(* Logix 5000 project; controller EFlo_iQ_Controller vendor 1 type 14 code 74 rev 20.12; software revision 20.01 *)

TASK MainTask (continuous, watchdog 500 ms) : MainProgram

MODULES
   Local : vendor 1 type 14 code 74 (1768Ctrl5Slot 0, Compact 0, rev 20.12)
      ENET : 1768-ENBT (1768 1, Ethernet 10.10.20.11, rev 3.1)
         EFlo_iQ : ETHERNET-MODULE (Ethernet 192.168.2.16, rev 1.1, Output RPI 10 ms)   // Graco E-Flo iQ Advanced Heat Map
END_MODULES

TYPE ActivePump :
STRUCT
   ControlBits : EFlo_iQ_Control_Bits;
   StatusBits : EFlo_iQ_Status_Bits;
   Information : EFlo_iQ_Pump_Information;
   AdditionalInformation : EFlo_iQ_Pump_Information_ActivePumpOnly;
   DispenseInformation : EFlo_iQ_Dispense_Information;
   StyleInformation : E_Flo_iQ_Style;
   HeartbeatLogic : EFlo_iQ_HeartbeatLogic;
   DataExchange : EFlo_iQ_Pump_Data_Exchange;
END_STRUCT
END_TYPE

TYPE E_Flo_iQ_Style :
STRUCT
   DesiredActiveStyleNumber : INT;
   StyleFieldbusPrechargeRequested : INT;   // XXXX.X bars
   StyleFieldbusFlowrateRequested : INT;   // XXXX cc/min
   StyleFieldbusShotSizeRequested : INT;   // XXXX.XX cc
   StyleFieldbusDValveOnDelayRequested : INT;   // XXXX ms
   StyleFieldbusDValveOffDelayRequested : INT;   // XXXX ms
   StyleFieldbusMotorOnDelayRequested : INT;   // XXXX ms
   StyleFieldbusMotorOffDelayRequested : INT;   // XXXX ms
   ActiveStyleLoaded : INT;
   ActiveStylePrecharge : INT;   // XXXX.X bars
   ActiveStyleFlowrate : INT;   // XXXX cc/min
   ActiveStyleShotSize : INT;   // XXXX.XX cc
   ActiveStyleDispenseValveOnDelay : INT;   // XXXX ms
   ActiveStyleDispenseValveOffDelay : INT;   // XXXX ms
   ActiveStyleMotorOnDelay : INT;   // XXXX ms
   ActiveStyleMotorOffDelay : INT;   // XXXX ms
   ActualStyleFieldbusRequestPrecharge : INT;   // XXXX.X bars
   ActualStyleFieldbusRequestFlowrate : INT;   // XXXX cc/min
   ActualStyleFieldbusRequestShotSize : INT;   // XXXX.XX cc
   ActualStyleFieldbusRequestDValveOnDeley : INT;   // XXXX ms
   ActualStyleFieldbusRequestDValveOffDeley : INT;   // XXXX ms
   ActualStyleFieldbusRequestMotorOnDelay : INT;   // XXXX ms
   ActualStyleFieldbusRequestMotorOffDelay : INT;   // XXXX ms
END_STRUCT
END_TYPE

TYPE EFlo_iQ_Control_Bits :
STRUCT
   SystemEnableRequest : BOOL;
   SystemDisableRequest : BOOL;
   PLCLockoutRequest : BOOL;
   StyleEnableSignal : BOOL;
   StyleGoSignal : BOOL;
   StyleDispenseCompleted : BOOL;
   TandemCrossoverRequest : BOOL;
   PrimingRequest : BOOL;
   ValveDepressurizationRequest : BOOL;
   PlatenDepressurizationRequest : BOOL;
   AutoDepressurizationCancelRequest : BOOL;
   AcknowledgeClearErrorsRequest : BOOL;
END_STRUCT
END_TYPE

TYPE EFlo_iQ_Dispense_Information :
STRUCT
   ActualAmountDispense : DINT;   // XXXX.XX cc
   ActualShotSizeRequested : DINT;   // XXXX.XX cc
END_STRUCT
END_TYPE

TYPE EFlo_iQ_HeartbeatLogic :
STRUCT
   HeartbeatFailure : BOOL;
   EFlo_iQ_Disconnected : BOOL;
   Heartbeat_HighMonitor : COUNTER;
   Heartbeat_LowMonitor : COUNTER;
   Heartbeat_MonitorTimer : TIMER;
   Heartbeat_StopMonitorTimer : BOOL;
END_STRUCT
END_TYPE

TYPE EFlo_iQ_Pump_Data_Exchange :
STRUCT
   PumpDataExchangeActiveCommand : INT;
   PumpDataExchangeActiveValue : DINT;
END_STRUCT
END_TYPE

TYPE EFlo_iQ_Pump_Information :
STRUCT
   ActualPumpFlowrate : INT;   // XXXX cc/min
   OutletPumpPressure : INT;   // XXXX.X bars
END_STRUCT
END_TYPE

TYPE EFlo_iQ_Pump_Information_ActivePumpOnly :
STRUCT
   ValvePressure : INT;   // XXXX.X bars
   PumpPosition : INT;   // X.XXXX inches
   PrimeFlowrateTarget : INT;   // XXXX cc/min
   PrimePressureTarget : INT;   // XXXX.X bars
END_STRUCT
END_TYPE

TYPE EFlo_iQ_Status_Bits :
STRUCT
   Heartbeat : BOOL;
   AutomationReady : BOOL;
   PLCControlActive : BOOL;
   SystemActive : BOOL;
   NoAlarmsPresent : BOOL;
   NoDeviationsPresent : BOOL;
   NoAdvisoriesPresent : BOOL;
   SystemReadyToDispense : BOOL;
   PrechargeDechargeActive : BOOL;
   DispenseInProcess : BOOL;
   DrumIsLow : BOOL;
   DrumIsEmpty : BOOL;
   PumpNotPrimed : BOOL;
   PumpInJobCycle : BOOL;
   PrimingActive : BOOL;
   ValveDepressurizationActive : BOOL;
   PlatenDepressurizationActive : BOOL;
   AutoDepressurizationActive : BOOL;
   AutoDepressurizationHappened : BOOL;
   PumpIsTryingToMove : BOOL;
   PumpIsActuallyMoving : BOOL;
   DispenseValveOpened : BOOL;
   PlatenValveOpened : BOOL;
   TandemActivePump : BOOL;   // 0 = Pump 1 1 = Pump 2
   iQModeActive : BOOL;
   ChangeoverHappenedDuringDispense : BOOL;
END_STRUCT
END_TYPE

TYPE EFlo_iQ_System_Data_Exchange :
STRUCT
   DesiredDataExchangeCommand : INT;
END_STRUCT
END_TYPE

TYPE Heat_Control_Bits :
STRUCT
   SystemEnabledRequest : BOOL;
   SystemDisabledRequest : BOOL;
   PLCLockoutRequest : BOOL;
   HeatOnRequest : BOOL;
   HeatOffRequest : BOOL;
   HeatSetbackRequest : BOOL;
   AcknowledgeClearErrors : BOOL;
END_STRUCT
END_TYPE

TYPE Heat_Data_Exchange :
STRUCT
   HeatDataExchangeActiveCommand : INT;
   HeatDataExchangeActiveValue : DINT;
   HeatDataExchangeDesiredCommand : INT;
   HeatDataExchangeDesiredValue : DINT;
END_STRUCT
END_TYPE

TYPE Heat_HeartbeatLogic :
STRUCT
   HeartbeatFailure : BOOL;
   Heat_Disconnected : BOOL;
   Heartbeat_HighMonitor : COUNTER;
   Heartbeat_LowMonitor : COUNTER;
   Heartbeat_MonitorTimer : TIMER;
   Heartbeat_StopMonitorTimer : BOOL;
END_STRUCT
END_TYPE

TYPE Heat_Information :
STRUCT
   ModuleHeatSoakTimeRemaining : INT;   // XXX seconds
END_STRUCT
END_TYPE

TYPE Heat_Module :
STRUCT
   Control_Bits : Heat_Control_Bits;
   Status_Bits : Heat_Status_Bits;
   DataExchange : Heat_Data_Exchange;
   Information : Heat_Information;
   Heartbeat_Logic : Heat_HeartbeatLogic;
END_STRUCT
END_TYPE

TYPE Heat_Status_Bits :
STRUCT
   HeartbeatToPLC : BOOL;
   SystemHeatEnabled : BOOL;
   PLCControlLockActive : BOOL;
   HeatIsOn : BOOL;
   HeatIsWarmingUp : BOOL;
   HeatIsAtTemperature : BOOL;
   HeatIsInTempeatureSoak : BOOL;
   HeatIsInSetback : BOOL;
   HeatIsOff : BOOL;
   NoHeatModuleAlarmsPresent : BOOL;
   NoHeatModuleDeviationsPresent : BOOL;
   NoHeatModuleAdvisoriesPresent : BOOL;
   NoHeatZonesAlarmsPresent : BOOL;
   NoHeatZonesDeviationsPresent : BOOL;
   NoHeatZonesAdvisoriesPresent : BOOL;
   HeatIdleTimeoutHappened : BOOL;
END_STRUCT
END_TYPE

TYPE InactivePump :
STRUCT
   StatusBits : EFlo_iQ_Status_Bits;
   Information : EFlo_iQ_Pump_Information;
   DataExchangeOutputs : EFlo_iQ_Pump_Data_Exchange;
   HeartbeatLogic : EFlo_iQ_HeartbeatLogic;
END_STRUCT
END_TYPE

VAR_GLOBAL   (* controller tags *)
   ActivePump : ActivePump;
   Heat_Module_One : Heat_Module := (Heartbeat_Logic.Heartbeat_HighMonitor.PRE := 2, Heartbeat_Logic.Heartbeat_LowMonitor.PRE := 2, Heartbeat_Logic.Heartbeat_MonitorTimer.PRE := 20000);
   Heat_Module_Two : Heat_Module := (Heartbeat_Logic.Heartbeat_HighMonitor.PRE := 2, Heartbeat_Logic.Heartbeat_LowMonitor.PRE := 2, Heartbeat_Logic.Heartbeat_MonitorTimer.PRE := 20000);
   InactivePump : InactivePump;
   PumpsDesiredDataExchange : EFlo_iQ_System_Data_Exchange;
END_VAR

PROGRAM MainProgram   (* main routine MainRoutine *)

ROUTINE EFlo_iQ_Data_Mapping   (* ladder *)
// Mapping_EFlo_iQ_Data_To_Tags
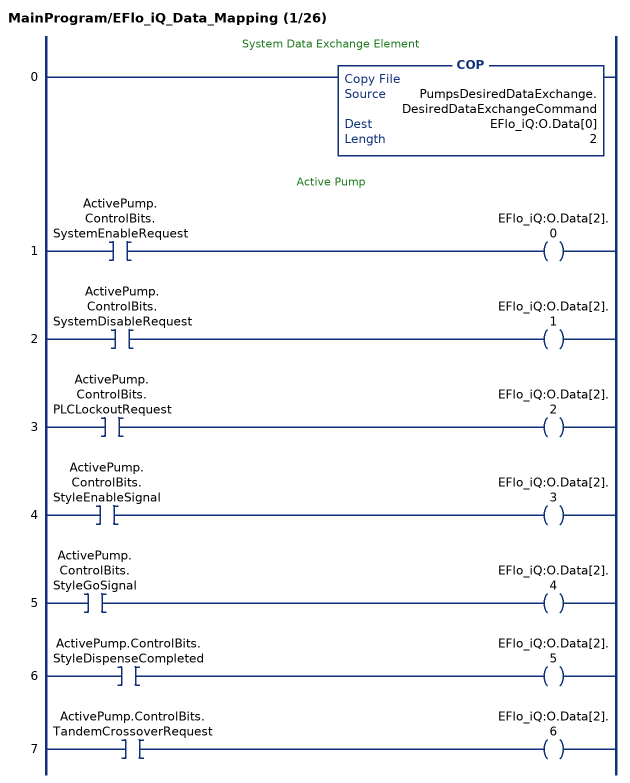
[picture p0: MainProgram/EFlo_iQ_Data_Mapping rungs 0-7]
   // System Data Exchange Element
   0: COP(PumpsDesiredDataExchange.DesiredDataExchangeCommand,EFlo_iQ:O.Data[0],2);
   // Active Pump
   1: XIC(ActivePump.ControlBits.SystemEnableRequest)OTE(EFlo_iQ:O.Data[2].0);
   2: XIC(ActivePump.ControlBits.SystemDisableRequest)OTE(EFlo_iQ:O.Data[2].1);
   3: XIC(ActivePump.ControlBits.PLCLockoutRequest)OTE(EFlo_iQ:O.Data[2].2);
   4: XIC(ActivePump.ControlBits.StyleEnableSignal)OTE(EFlo_iQ:O.Data[2].3);
   5: XIC(ActivePump.ControlBits.StyleGoSignal)OTE(EFlo_iQ:O.Data[2].4);
   6: XIC(ActivePump.ControlBits.StyleDispenseCompleted)OTE(EFlo_iQ:O.Data[2].5);
   7: XIC(ActivePump.ControlBits.TandemCrossoverRequest)OTE(EFlo_iQ:O.Data[2].6);
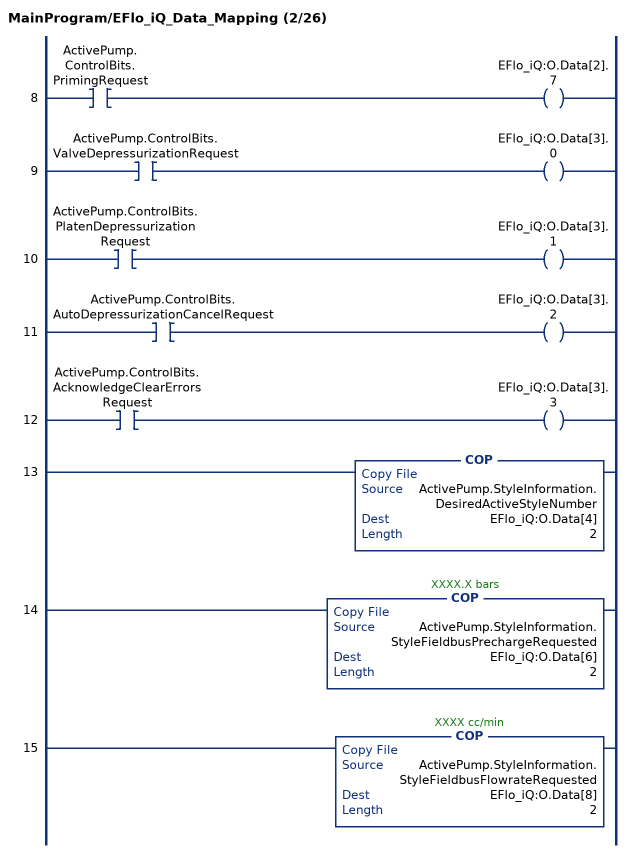
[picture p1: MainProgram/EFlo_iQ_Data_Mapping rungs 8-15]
   8: XIC(ActivePump.ControlBits.PrimingRequest)OTE(EFlo_iQ:O.Data[2].7);
   9: XIC(ActivePump.ControlBits.ValveDepressurizationRequest)OTE(EFlo_iQ:O.Data[3].0);
   10: XIC(ActivePump.ControlBits.PlatenDepressurizationRequest)OTE(EFlo_iQ:O.Data[3].1);
   11: XIC(ActivePump.ControlBits.AutoDepressurizationCancelRequest)OTE(EFlo_iQ:O.Data[3].2);
   12: XIC(ActivePump.ControlBits.AcknowledgeClearErrorsRequest)OTE(EFlo_iQ:O.Data[3].3);
   13: COP(ActivePump.StyleInformation.DesiredActiveStyleNumber,EFlo_iQ:O.Data[4],2);
   14: COP(ActivePump.StyleInformation.StyleFieldbusPrechargeRequested,EFlo_iQ:O.Data[6],2);
   15: COP(ActivePump.StyleInformation.StyleFieldbusFlowrateRequested,EFlo_iQ:O.Data[8],2);
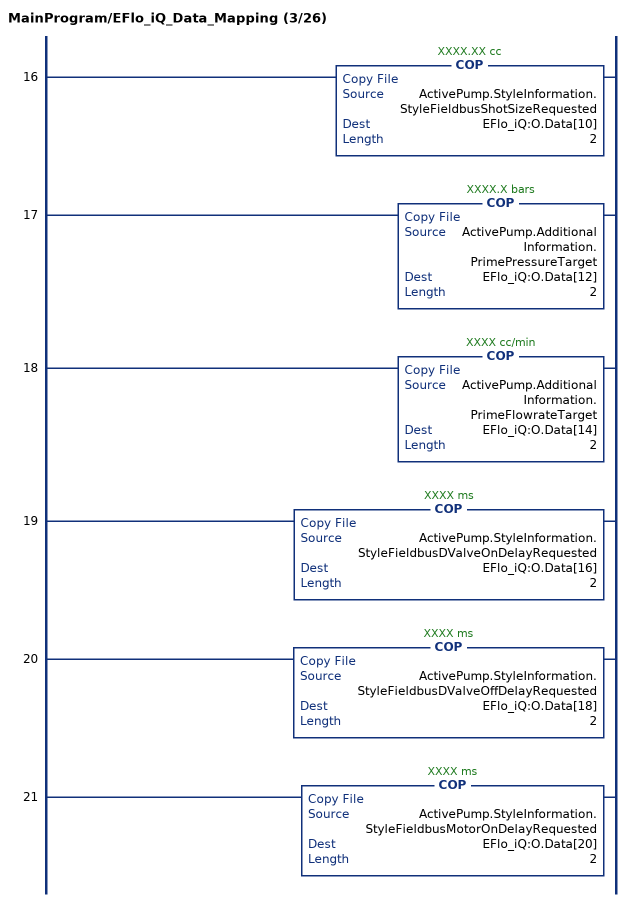
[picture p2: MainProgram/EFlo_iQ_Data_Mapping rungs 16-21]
   16: COP(ActivePump.StyleInformation.StyleFieldbusShotSizeRequested,EFlo_iQ:O.Data[10],2);
   17: COP(ActivePump.AdditionalInformation.PrimePressureTarget,EFlo_iQ:O.Data[12],2);
   18: COP(ActivePump.AdditionalInformation.PrimeFlowrateTarget,EFlo_iQ:O.Data[14],2);
   19: COP(ActivePump.StyleInformation.StyleFieldbusDValveOnDelayRequested,EFlo_iQ:O.Data[16],2);
   20: COP(ActivePump.StyleInformation.StyleFieldbusDValveOffDelayRequested,EFlo_iQ:O.Data[18],2);
   21: COP(ActivePump.StyleInformation.StyleFieldbusMotorOnDelayRequested,EFlo_iQ:O.Data[20],2);
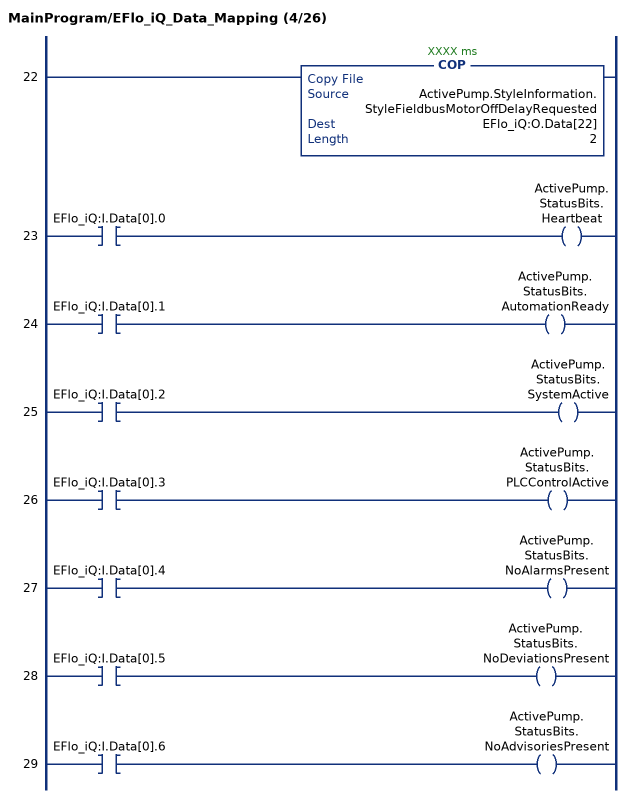
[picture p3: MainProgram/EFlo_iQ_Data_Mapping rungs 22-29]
   22: COP(ActivePump.StyleInformation.StyleFieldbusMotorOffDelayRequested,EFlo_iQ:O.Data[22],2);
   23: XIC(EFlo_iQ:I.Data[0].0)OTE(ActivePump.StatusBits.Heartbeat);
   24: XIC(EFlo_iQ:I.Data[0].1)OTE(ActivePump.StatusBits.AutomationReady);
   25: XIC(EFlo_iQ:I.Data[0].2)OTE(ActivePump.StatusBits.SystemActive);
   26: XIC(EFlo_iQ:I.Data[0].3)OTE(ActivePump.StatusBits.PLCControlActive);
   27: XIC(EFlo_iQ:I.Data[0].4)OTE(ActivePump.StatusBits.NoAlarmsPresent);
   28: XIC(EFlo_iQ:I.Data[0].5)OTE(ActivePump.StatusBits.NoDeviationsPresent);
   29: XIC(EFlo_iQ:I.Data[0].6)OTE(ActivePump.StatusBits.NoAdvisoriesPresent);
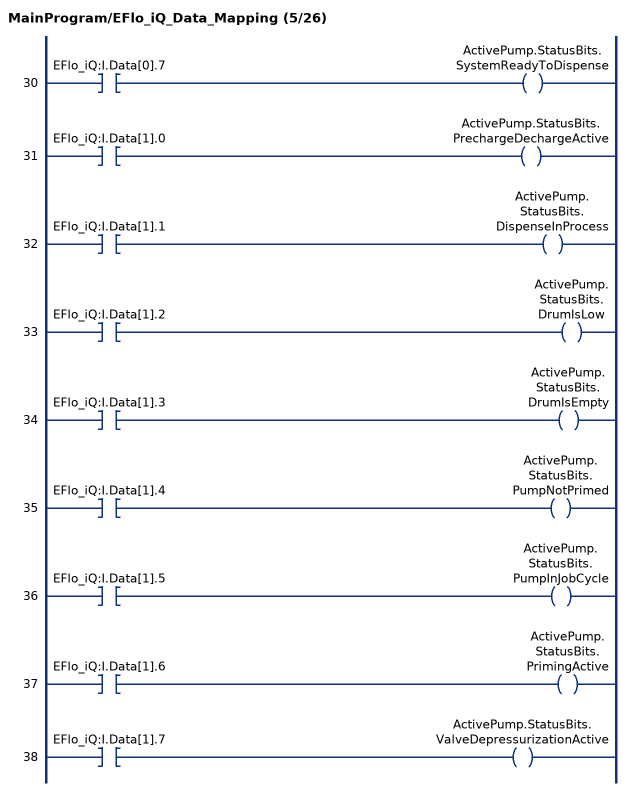
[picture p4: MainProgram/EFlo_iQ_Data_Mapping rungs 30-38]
   30: XIC(EFlo_iQ:I.Data[0].7)OTE(ActivePump.StatusBits.SystemReadyToDispense);
   31: XIC(EFlo_iQ:I.Data[1].0)OTE(ActivePump.StatusBits.PrechargeDechargeActive);
   32: XIC(EFlo_iQ:I.Data[1].1)OTE(ActivePump.StatusBits.DispenseInProcess);
   33: XIC(EFlo_iQ:I.Data[1].2)OTE(ActivePump.StatusBits.DrumIsLow);
   34: XIC(EFlo_iQ:I.Data[1].3)OTE(ActivePump.StatusBits.DrumIsEmpty);
   35: XIC(EFlo_iQ:I.Data[1].4)OTE(ActivePump.StatusBits.PumpNotPrimed);
   36: XIC(EFlo_iQ:I.Data[1].5)OTE(ActivePump.StatusBits.PumpInJobCycle);
   37: XIC(EFlo_iQ:I.Data[1].6)OTE(ActivePump.StatusBits.PrimingActive);
   38: XIC(EFlo_iQ:I.Data[1].7)OTE(ActivePump.StatusBits.ValveDepressurizationActive);
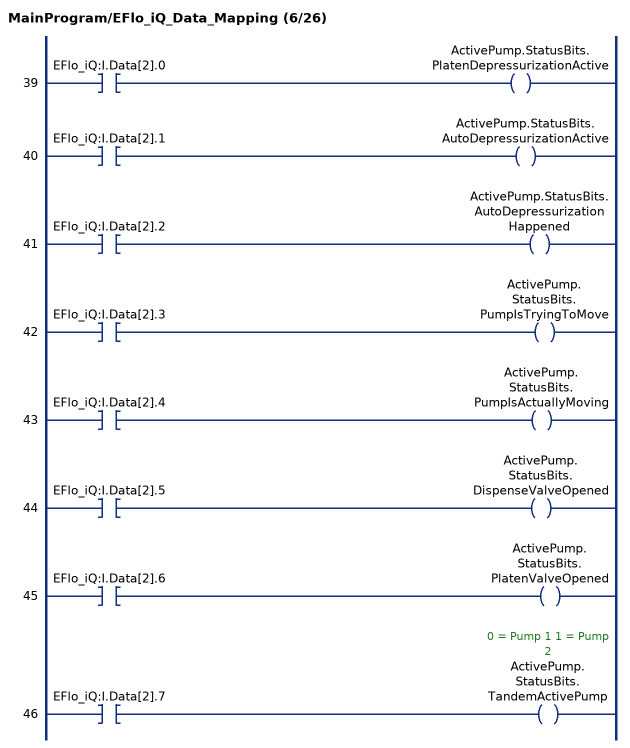
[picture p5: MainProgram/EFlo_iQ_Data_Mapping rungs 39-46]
   39: XIC(EFlo_iQ:I.Data[2].0)OTE(ActivePump.StatusBits.PlatenDepressurizationActive);
   40: XIC(EFlo_iQ:I.Data[2].1)OTE(ActivePump.StatusBits.AutoDepressurizationActive);
   41: XIC(EFlo_iQ:I.Data[2].2)OTE(ActivePump.StatusBits.AutoDepressurizationHappened);
   42: XIC(EFlo_iQ:I.Data[2].3)OTE(ActivePump.StatusBits.PumpIsTryingToMove);
   43: XIC(EFlo_iQ:I.Data[2].4)OTE(ActivePump.StatusBits.PumpIsActuallyMoving);
   44: XIC(EFlo_iQ:I.Data[2].5)OTE(ActivePump.StatusBits.DispenseValveOpened);
   45: XIC(EFlo_iQ:I.Data[2].6)OTE(ActivePump.StatusBits.PlatenValveOpened);
   46: XIC(EFlo_iQ:I.Data[2].7)OTE(ActivePump.StatusBits.TandemActivePump);
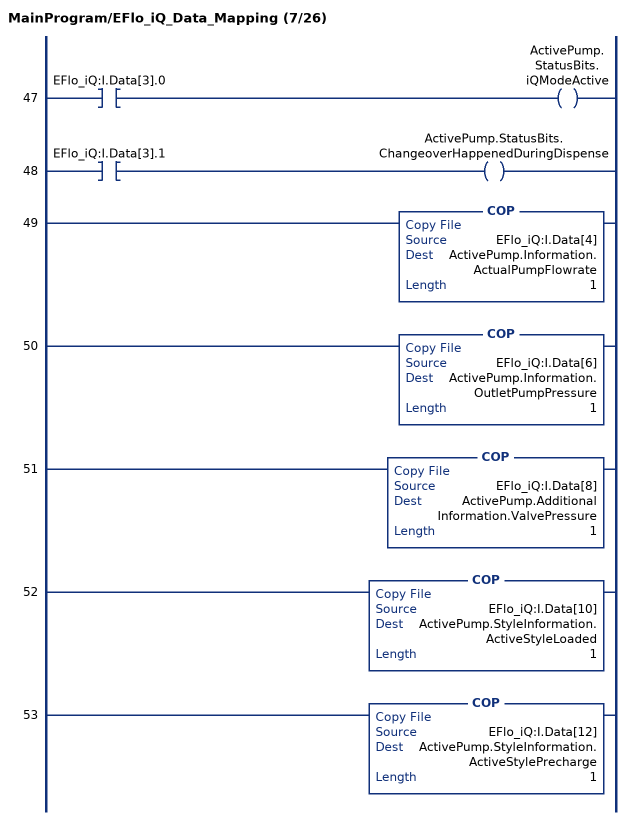
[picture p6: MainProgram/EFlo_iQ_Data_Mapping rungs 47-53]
   47: XIC(EFlo_iQ:I.Data[3].0)OTE(ActivePump.StatusBits.iQModeActive);
   48: XIC(EFlo_iQ:I.Data[3].1)OTE(ActivePump.StatusBits.ChangeoverHappenedDuringDispense);
   49: COP(EFlo_iQ:I.Data[4],ActivePump.Information.ActualPumpFlowrate,1);
   50: COP(EFlo_iQ:I.Data[6],ActivePump.Information.OutletPumpPressure,1);
   51: COP(EFlo_iQ:I.Data[8],ActivePump.AdditionalInformation.ValvePressure,1);
   52: COP(EFlo_iQ:I.Data[10],ActivePump.StyleInformation.ActiveStyleLoaded,1);
   53: COP(EFlo_iQ:I.Data[12],ActivePump.StyleInformation.ActiveStylePrecharge,1);
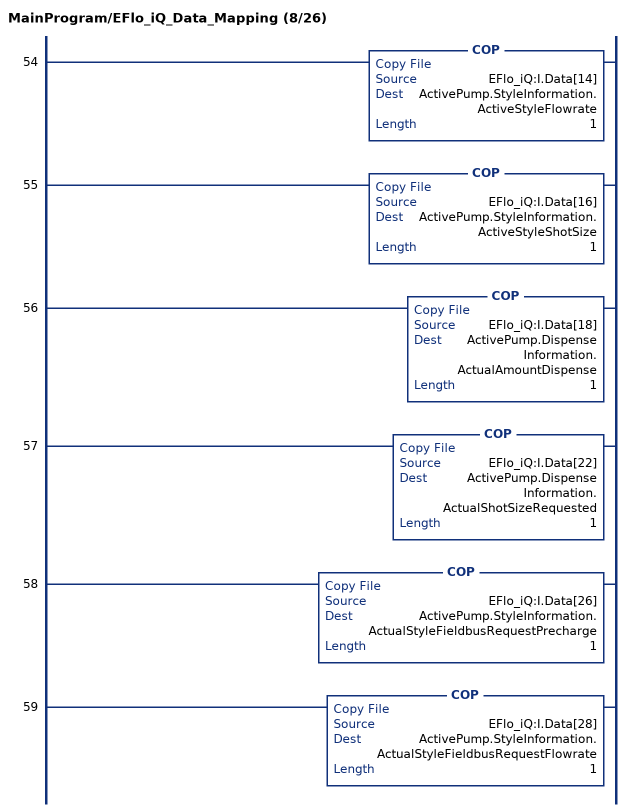
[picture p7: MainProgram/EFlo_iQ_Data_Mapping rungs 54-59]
   54: COP(EFlo_iQ:I.Data[14],ActivePump.StyleInformation.ActiveStyleFlowrate,1);
   55: COP(EFlo_iQ:I.Data[16],ActivePump.StyleInformation.ActiveStyleShotSize,1);
   56: COP(EFlo_iQ:I.Data[18],ActivePump.DispenseInformation.ActualAmountDispense,1);
   57: COP(EFlo_iQ:I.Data[22],ActivePump.DispenseInformation.ActualShotSizeRequested,1);
   58: COP(EFlo_iQ:I.Data[26],ActivePump.StyleInformation.ActualStyleFieldbusRequestPrecharge,1);
   59: COP(EFlo_iQ:I.Data[28],ActivePump.StyleInformation.ActualStyleFieldbusRequestFlowrate,1);
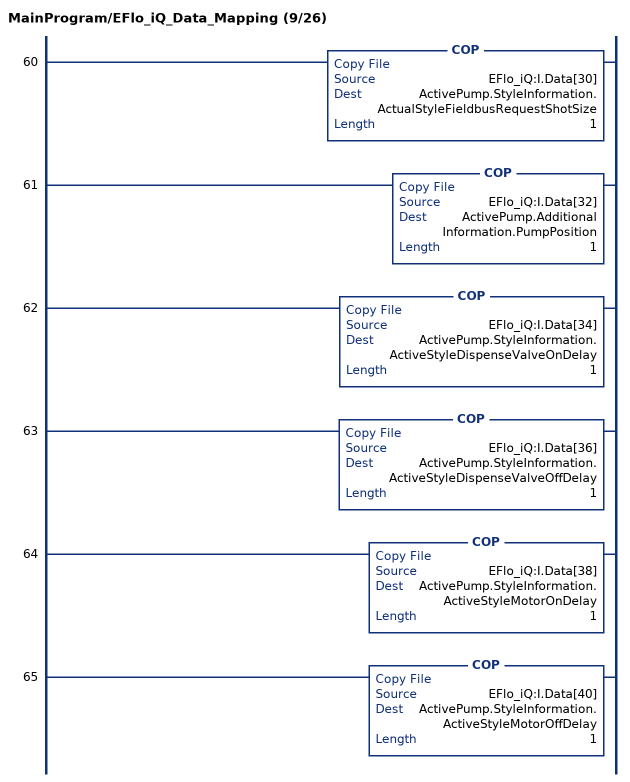
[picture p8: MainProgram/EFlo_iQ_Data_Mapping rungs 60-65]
   60: COP(EFlo_iQ:I.Data[30],ActivePump.StyleInformation.ActualStyleFieldbusRequestShotSize,1);
   61: COP(EFlo_iQ:I.Data[32],ActivePump.AdditionalInformation.PumpPosition,1);
   62: COP(EFlo_iQ:I.Data[34],ActivePump.StyleInformation.ActiveStyleDispenseValveOnDelay,1);
   63: COP(EFlo_iQ:I.Data[36],ActivePump.StyleInformation.ActiveStyleDispenseValveOffDelay,1);
   64: COP(EFlo_iQ:I.Data[38],ActivePump.StyleInformation.ActiveStyleMotorOnDelay,1);
   65: COP(EFlo_iQ:I.Data[40],ActivePump.StyleInformation.ActiveStyleMotorOffDelay,1);
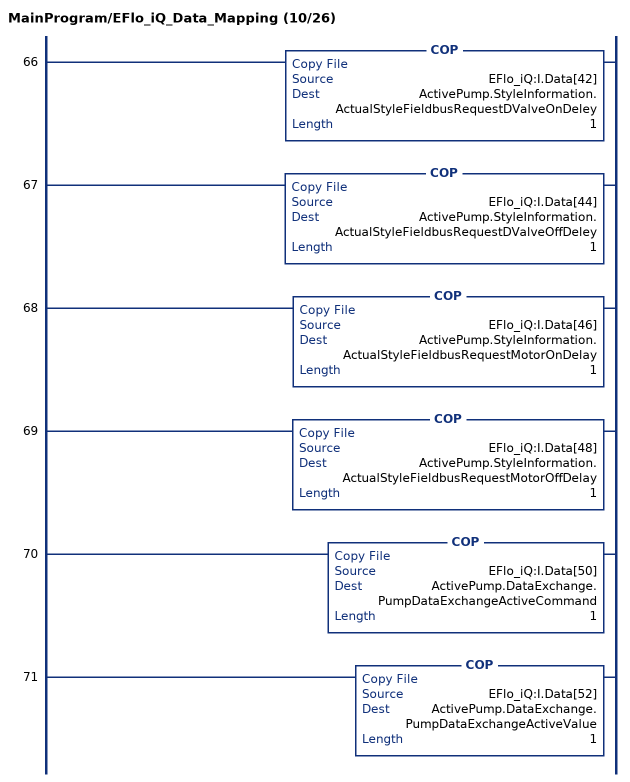
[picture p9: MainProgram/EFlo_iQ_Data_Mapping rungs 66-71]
   66: COP(EFlo_iQ:I.Data[42],ActivePump.StyleInformation.ActualStyleFieldbusRequestDValveOnDeley,1);
   67: COP(EFlo_iQ:I.Data[44],ActivePump.StyleInformation.ActualStyleFieldbusRequestDValveOffDeley,1);
   68: COP(EFlo_iQ:I.Data[46],ActivePump.StyleInformation.ActualStyleFieldbusRequestMotorOnDelay,1);
   69: COP(EFlo_iQ:I.Data[48],ActivePump.StyleInformation.ActualStyleFieldbusRequestMotorOffDelay,1);
   70: COP(EFlo_iQ:I.Data[50],ActivePump.DataExchange.PumpDataExchangeActiveCommand,1);
   71: COP(EFlo_iQ:I.Data[52],ActivePump.DataExchange.PumpDataExchangeActiveValue,1);
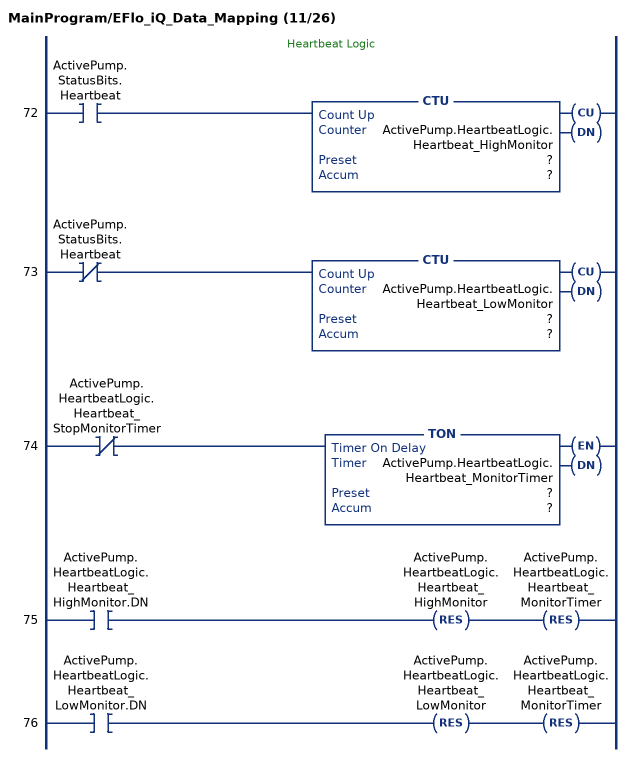
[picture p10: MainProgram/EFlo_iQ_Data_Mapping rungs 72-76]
   // Heartbeat Logic
   72: XIC(ActivePump.StatusBits.Heartbeat)CTU(ActivePump.HeartbeatLogic.Heartbeat_HighMonitor,?,?);
   73: XIO(ActivePump.StatusBits.Heartbeat)CTU(ActivePump.HeartbeatLogic.Heartbeat_LowMonitor,?,?);
   74: XIO(ActivePump.HeartbeatLogic.Heartbeat_StopMonitorTimer)TON(ActivePump.HeartbeatLogic.Heartbeat_MonitorTimer,?,?);
   75: XIC(ActivePump.HeartbeatLogic.Heartbeat_HighMonitor.DN)RES(ActivePump.HeartbeatLogic.Heartbeat_HighMonitor)RES(ActivePump.HeartbeatLogic.Heartbeat_MonitorTimer);
   76: XIC(ActivePump.HeartbeatLogic.Heartbeat_LowMonitor.DN)RES(ActivePump.HeartbeatLogic.Heartbeat_LowMonitor)RES(ActivePump.HeartbeatLogic.Heartbeat_MonitorTimer);
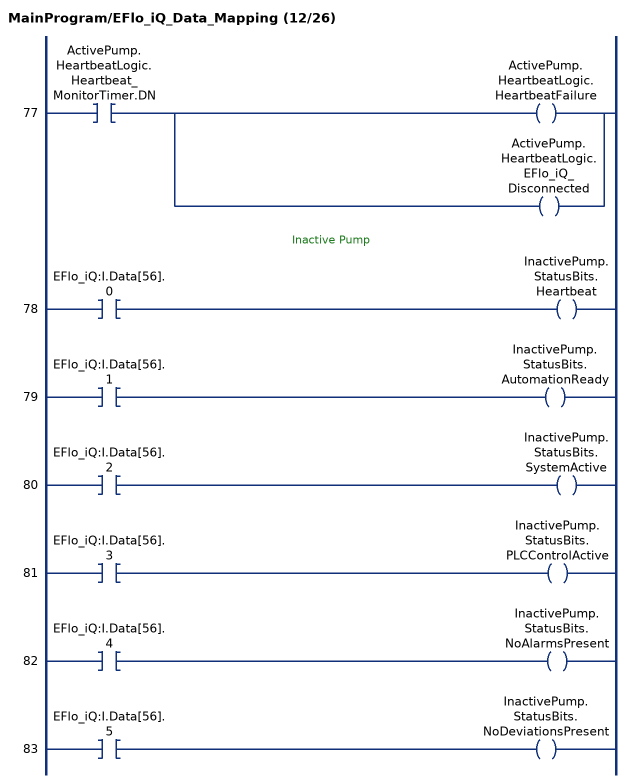
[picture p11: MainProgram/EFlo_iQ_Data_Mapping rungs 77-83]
   77: XIC(ActivePump.HeartbeatLogic.Heartbeat_MonitorTimer.DN)[OTE(ActivePump.HeartbeatLogic.HeartbeatFailure) ,OTE(ActivePump.HeartbeatLogic.EFlo_iQ_Disconnected) ];
   // Inactive Pump
   78: XIC(EFlo_iQ:I.Data[56].0)OTE(InactivePump.StatusBits.Heartbeat);
   79: XIC(EFlo_iQ:I.Data[56].1)OTE(InactivePump.StatusBits.AutomationReady);
   80: XIC(EFlo_iQ:I.Data[56].2)OTE(InactivePump.StatusBits.SystemActive);
   81: XIC(EFlo_iQ:I.Data[56].3)OTE(InactivePump.StatusBits.PLCControlActive);
   82: XIC(EFlo_iQ:I.Data[56].4)OTE(InactivePump.StatusBits.NoAlarmsPresent);
   83: XIC(EFlo_iQ:I.Data[56].5)OTE(InactivePump.StatusBits.NoDeviationsPresent);
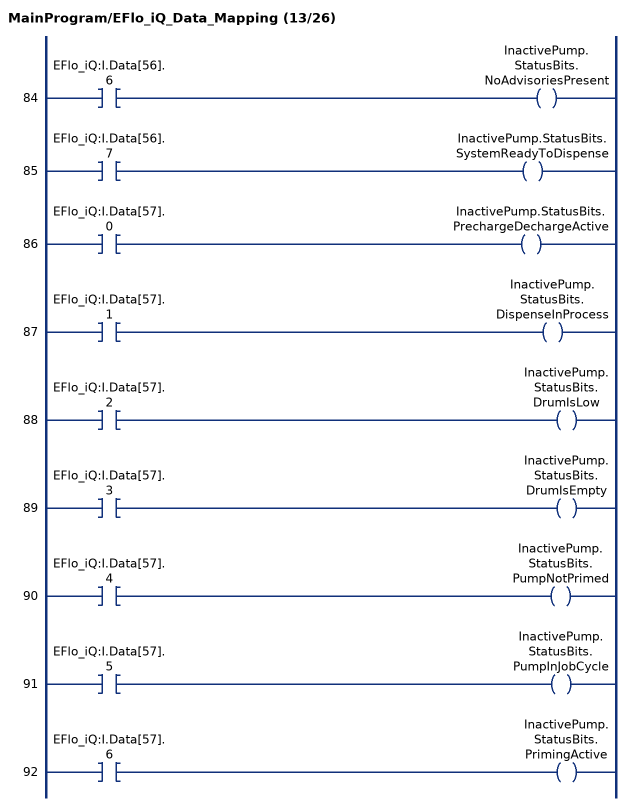
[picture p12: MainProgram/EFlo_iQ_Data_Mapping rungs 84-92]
   84: XIC(EFlo_iQ:I.Data[56].6)OTE(InactivePump.StatusBits.NoAdvisoriesPresent);
   85: XIC(EFlo_iQ:I.Data[56].7)OTE(InactivePump.StatusBits.SystemReadyToDispense);
   86: XIC(EFlo_iQ:I.Data[57].0)OTE(InactivePump.StatusBits.PrechargeDechargeActive);
   87: XIC(EFlo_iQ:I.Data[57].1)OTE(InactivePump.StatusBits.DispenseInProcess);
   88: XIC(EFlo_iQ:I.Data[57].2)OTE(InactivePump.StatusBits.DrumIsLow);
   89: XIC(EFlo_iQ:I.Data[57].3)OTE(InactivePump.StatusBits.DrumIsEmpty);
   90: XIC(EFlo_iQ:I.Data[57].4)OTE(InactivePump.StatusBits.PumpNotPrimed);
   91: XIC(EFlo_iQ:I.Data[57].5)OTE(InactivePump.StatusBits.PumpInJobCycle);
   92: XIC(EFlo_iQ:I.Data[57].6)OTE(InactivePump.StatusBits.PrimingActive);
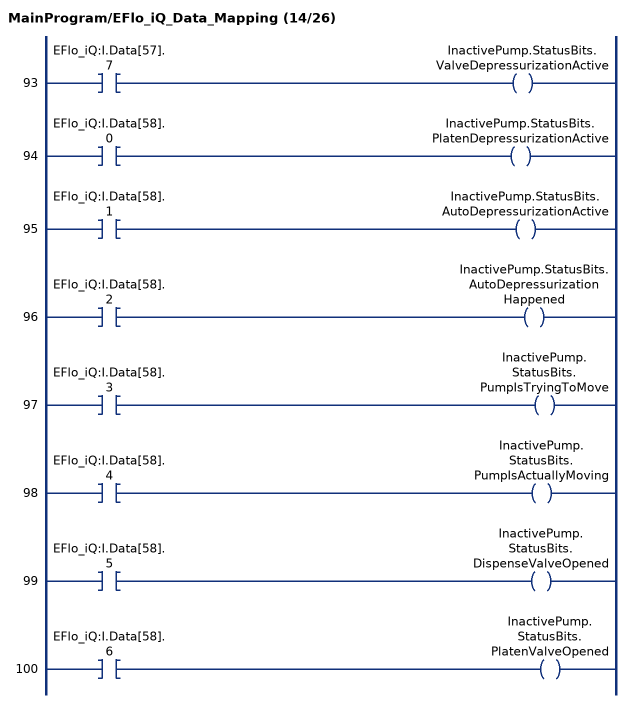
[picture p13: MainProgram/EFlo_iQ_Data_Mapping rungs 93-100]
   93: XIC(EFlo_iQ:I.Data[57].7)OTE(InactivePump.StatusBits.ValveDepressurizationActive);
   94: XIC(EFlo_iQ:I.Data[58].0)OTE(InactivePump.StatusBits.PlatenDepressurizationActive);
   95: XIC(EFlo_iQ:I.Data[58].1)OTE(InactivePump.StatusBits.AutoDepressurizationActive);
   96: XIC(EFlo_iQ:I.Data[58].2)OTE(InactivePump.StatusBits.AutoDepressurizationHappened);
   97: XIC(EFlo_iQ:I.Data[58].3)OTE(InactivePump.StatusBits.PumpIsTryingToMove);
   98: XIC(EFlo_iQ:I.Data[58].4)OTE(InactivePump.StatusBits.PumpIsActuallyMoving);
   99: XIC(EFlo_iQ:I.Data[58].5)OTE(InactivePump.StatusBits.DispenseValveOpened);
   100: XIC(EFlo_iQ:I.Data[58].6)OTE(InactivePump.StatusBits.PlatenValveOpened);
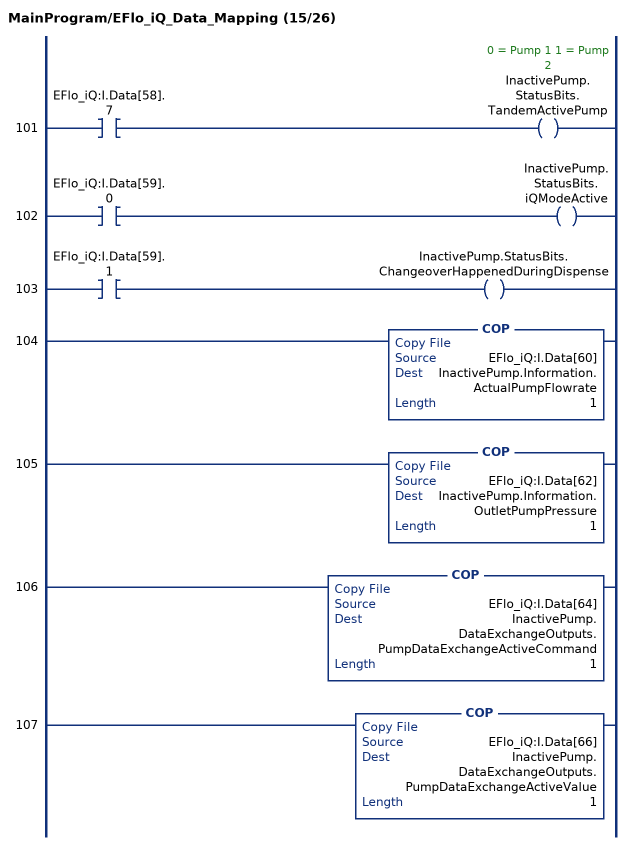
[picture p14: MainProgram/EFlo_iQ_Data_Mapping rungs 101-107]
   101: XIC(EFlo_iQ:I.Data[58].7)OTE(InactivePump.StatusBits.TandemActivePump);
   102: XIC(EFlo_iQ:I.Data[59].0)OTE(InactivePump.StatusBits.iQModeActive);
   103: XIC(EFlo_iQ:I.Data[59].1)OTE(InactivePump.StatusBits.ChangeoverHappenedDuringDispense);
   104: COP(EFlo_iQ:I.Data[60],InactivePump.Information.ActualPumpFlowrate,1);
   105: COP(EFlo_iQ:I.Data[62],InactivePump.Information.OutletPumpPressure,1);
   106: COP(EFlo_iQ:I.Data[64],InactivePump.DataExchangeOutputs.PumpDataExchangeActiveCommand,1);
   107: COP(EFlo_iQ:I.Data[66],InactivePump.DataExchangeOutputs.PumpDataExchangeActiveValue,1);
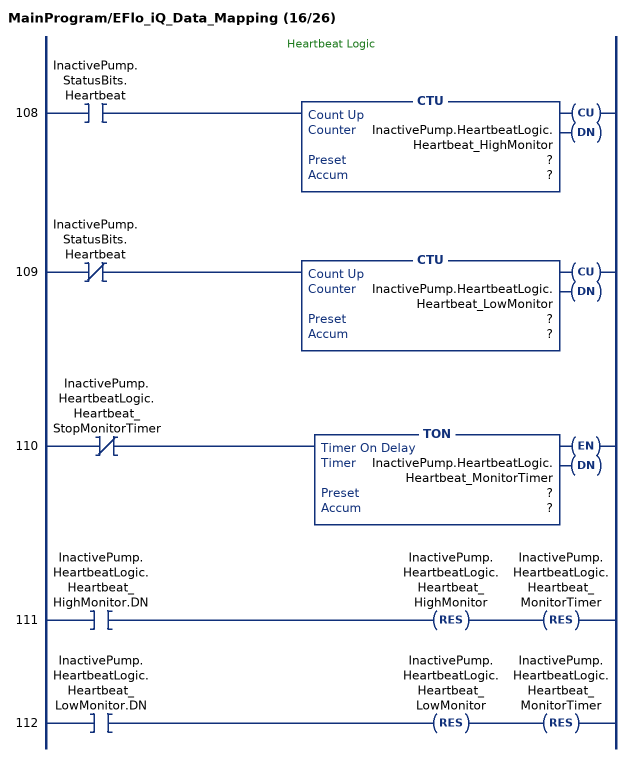
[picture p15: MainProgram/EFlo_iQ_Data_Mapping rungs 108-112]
   // Heartbeat Logic
   108: XIC(InactivePump.StatusBits.Heartbeat)CTU(InactivePump.HeartbeatLogic.Heartbeat_HighMonitor,?,?);
   109: XIO(InactivePump.StatusBits.Heartbeat)CTU(InactivePump.HeartbeatLogic.Heartbeat_LowMonitor,?,?);
   110: XIO(InactivePump.HeartbeatLogic.Heartbeat_StopMonitorTimer)TON(InactivePump.HeartbeatLogic.Heartbeat_MonitorTimer,?,?);
   111: XIC(InactivePump.HeartbeatLogic.Heartbeat_HighMonitor.DN)RES(InactivePump.HeartbeatLogic.Heartbeat_HighMonitor)RES(InactivePump.HeartbeatLogic.Heartbeat_MonitorTimer);
   112: XIC(InactivePump.HeartbeatLogic.Heartbeat_LowMonitor.DN)RES(InactivePump.HeartbeatLogic.Heartbeat_LowMonitor)RES(InactivePump.HeartbeatLogic.Heartbeat_MonitorTimer);
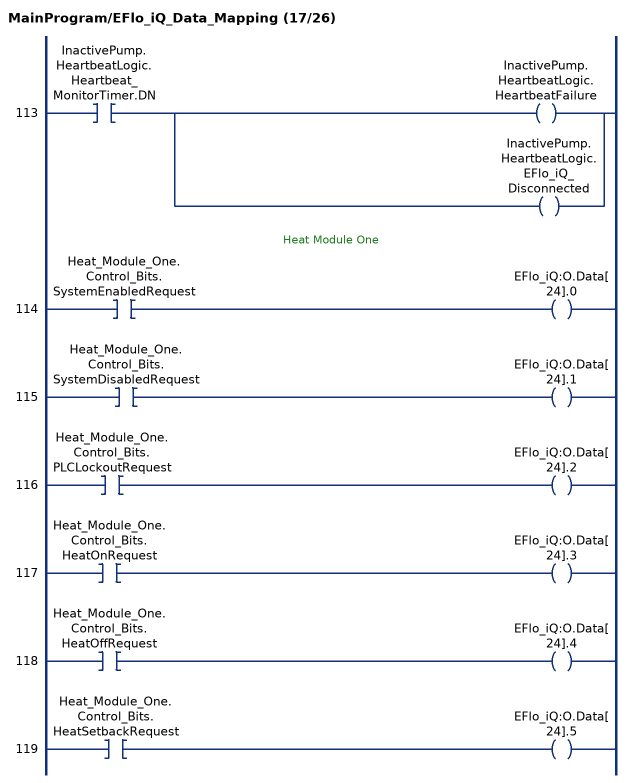
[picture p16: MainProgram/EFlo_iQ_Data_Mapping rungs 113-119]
   113: XIC(InactivePump.HeartbeatLogic.Heartbeat_MonitorTimer.DN)[OTE(InactivePump.HeartbeatLogic.HeartbeatFailure) ,OTE(InactivePump.HeartbeatLogic.EFlo_iQ_Disconnected) ];
   // Heat Module One
   114: XIC(Heat_Module_One.Control_Bits.SystemEnabledRequest)OTE(EFlo_iQ:O.Data[24].0);
   115: XIC(Heat_Module_One.Control_Bits.SystemDisabledRequest)OTE(EFlo_iQ:O.Data[24].1);
   116: XIC(Heat_Module_One.Control_Bits.PLCLockoutRequest)OTE(EFlo_iQ:O.Data[24].2);
   117: XIC(Heat_Module_One.Control_Bits.HeatOnRequest)OTE(EFlo_iQ:O.Data[24].3);
   118: XIC(Heat_Module_One.Control_Bits.HeatOffRequest)OTE(EFlo_iQ:O.Data[24].4);
   119: XIC(Heat_Module_One.Control_Bits.HeatSetbackRequest)OTE(EFlo_iQ:O.Data[24].5);
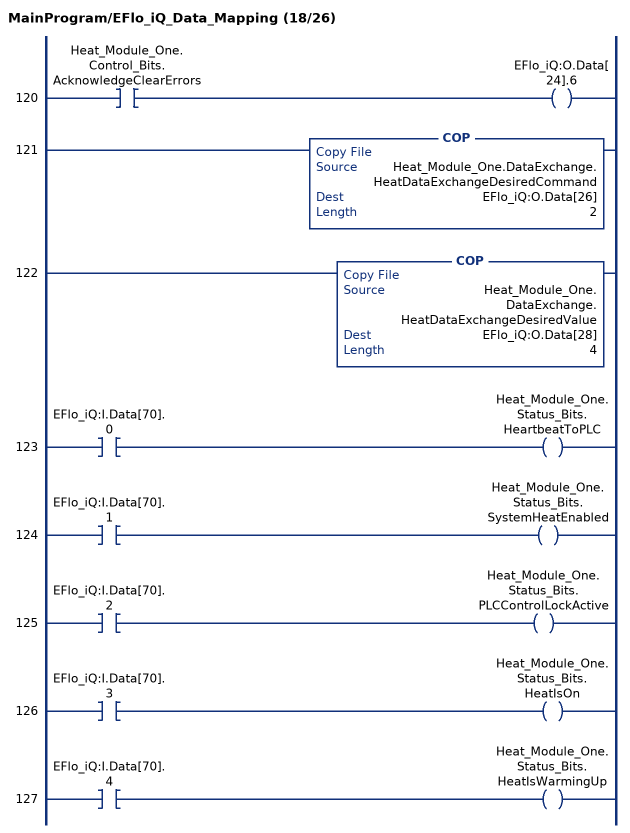
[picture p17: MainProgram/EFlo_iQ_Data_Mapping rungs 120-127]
   120: XIC(Heat_Module_One.Control_Bits.AcknowledgeClearErrors)OTE(EFlo_iQ:O.Data[24].6);
   121: COP(Heat_Module_One.DataExchange.HeatDataExchangeDesiredCommand,EFlo_iQ:O.Data[26],2);
   122: COP(Heat_Module_One.DataExchange.HeatDataExchangeDesiredValue,EFlo_iQ:O.Data[28],4);
   123: XIC(EFlo_iQ:I.Data[70].0)OTE(Heat_Module_One.Status_Bits.HeartbeatToPLC);
   124: XIC(EFlo_iQ:I.Data[70].1)OTE(Heat_Module_One.Status_Bits.SystemHeatEnabled);
   125: XIC(EFlo_iQ:I.Data[70].2)OTE(Heat_Module_One.Status_Bits.PLCControlLockActive);
   126: XIC(EFlo_iQ:I.Data[70].3)OTE(Heat_Module_One.Status_Bits.HeatIsOn);
   127: XIC(EFlo_iQ:I.Data[70].4)OTE(Heat_Module_One.Status_Bits.HeatIsWarmingUp);
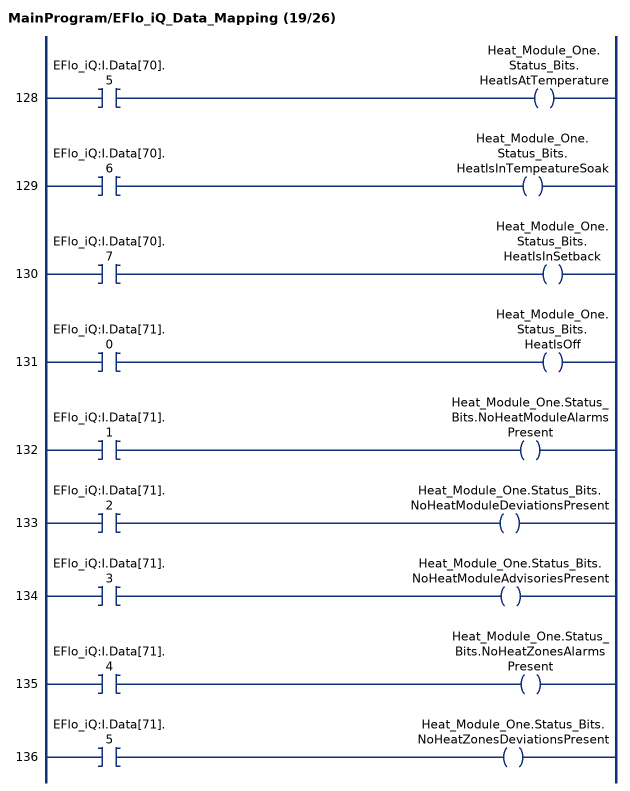
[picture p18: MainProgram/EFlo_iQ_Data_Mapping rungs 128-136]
   128: XIC(EFlo_iQ:I.Data[70].5)OTE(Heat_Module_One.Status_Bits.HeatIsAtTemperature);
   129: XIC(EFlo_iQ:I.Data[70].6)OTE(Heat_Module_One.Status_Bits.HeatIsInTempeatureSoak);
   130: XIC(EFlo_iQ:I.Data[70].7)OTE(Heat_Module_One.Status_Bits.HeatIsInSetback);
   131: XIC(EFlo_iQ:I.Data[71].0)OTE(Heat_Module_One.Status_Bits.HeatIsOff);
   132: XIC(EFlo_iQ:I.Data[71].1)OTE(Heat_Module_One.Status_Bits.NoHeatModuleAlarmsPresent);
   133: XIC(EFlo_iQ:I.Data[71].2)OTE(Heat_Module_One.Status_Bits.NoHeatModuleDeviationsPresent);
   134: XIC(EFlo_iQ:I.Data[71].3)OTE(Heat_Module_One.Status_Bits.NoHeatModuleAdvisoriesPresent);
   135: XIC(EFlo_iQ:I.Data[71].4)OTE(Heat_Module_One.Status_Bits.NoHeatZonesAlarmsPresent);
   136: XIC(EFlo_iQ:I.Data[71].5)OTE(Heat_Module_One.Status_Bits.NoHeatZonesDeviationsPresent);
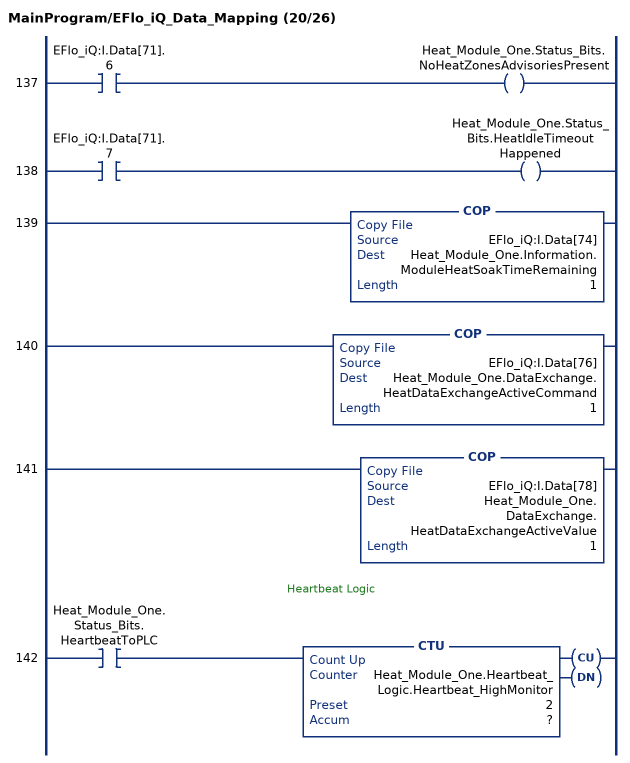
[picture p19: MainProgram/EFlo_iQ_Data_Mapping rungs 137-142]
   137: XIC(EFlo_iQ:I.Data[71].6)OTE(Heat_Module_One.Status_Bits.NoHeatZonesAdvisoriesPresent);
   138: XIC(EFlo_iQ:I.Data[71].7)OTE(Heat_Module_One.Status_Bits.HeatIdleTimeoutHappened);
   139: COP(EFlo_iQ:I.Data[74],Heat_Module_One.Information.ModuleHeatSoakTimeRemaining,1);
   140: COP(EFlo_iQ:I.Data[76],Heat_Module_One.DataExchange.HeatDataExchangeActiveCommand,1);
   141: COP(EFlo_iQ:I.Data[78],Heat_Module_One.DataExchange.HeatDataExchangeActiveValue,1);
   // Heartbeat Logic
   142: XIC(Heat_Module_One.Status_Bits.HeartbeatToPLC)CTU(Heat_Module_One.Heartbeat_Logic.Heartbeat_HighMonitor,?,?);
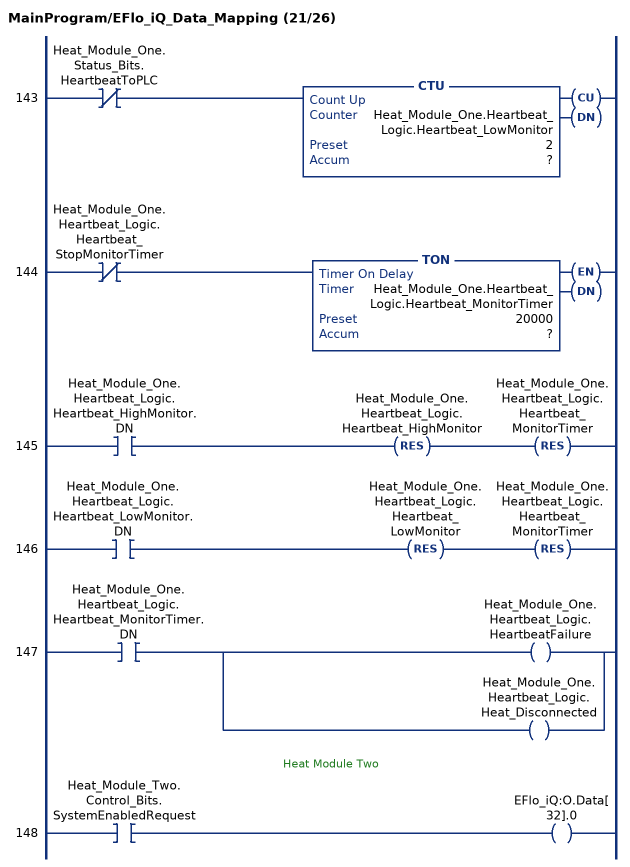
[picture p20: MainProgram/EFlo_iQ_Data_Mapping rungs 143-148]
   143: XIO(Heat_Module_One.Status_Bits.HeartbeatToPLC)CTU(Heat_Module_One.Heartbeat_Logic.Heartbeat_LowMonitor,?,?);
   144: XIO(Heat_Module_One.Heartbeat_Logic.Heartbeat_StopMonitorTimer)TON(Heat_Module_One.Heartbeat_Logic.Heartbeat_MonitorTimer,?,?);
   145: XIC(Heat_Module_One.Heartbeat_Logic.Heartbeat_HighMonitor.DN)RES(Heat_Module_One.Heartbeat_Logic.Heartbeat_HighMonitor)RES(Heat_Module_One.Heartbeat_Logic.Heartbeat_MonitorTimer);
   146: XIC(Heat_Module_One.Heartbeat_Logic.Heartbeat_LowMonitor.DN)RES(Heat_Module_One.Heartbeat_Logic.Heartbeat_LowMonitor)RES(Heat_Module_One.Heartbeat_Logic.Heartbeat_MonitorTimer);
   147: XIC(Heat_Module_One.Heartbeat_Logic.Heartbeat_MonitorTimer.DN)[OTE(Heat_Module_One.Heartbeat_Logic.HeartbeatFailure) ,OTE(Heat_Module_One.Heartbeat_Logic.Heat_Disconnected) ];
   // Heat Module Two
   148: XIC(Heat_Module_Two.Control_Bits.SystemEnabledRequest)OTE(EFlo_iQ:O.Data[32].0);
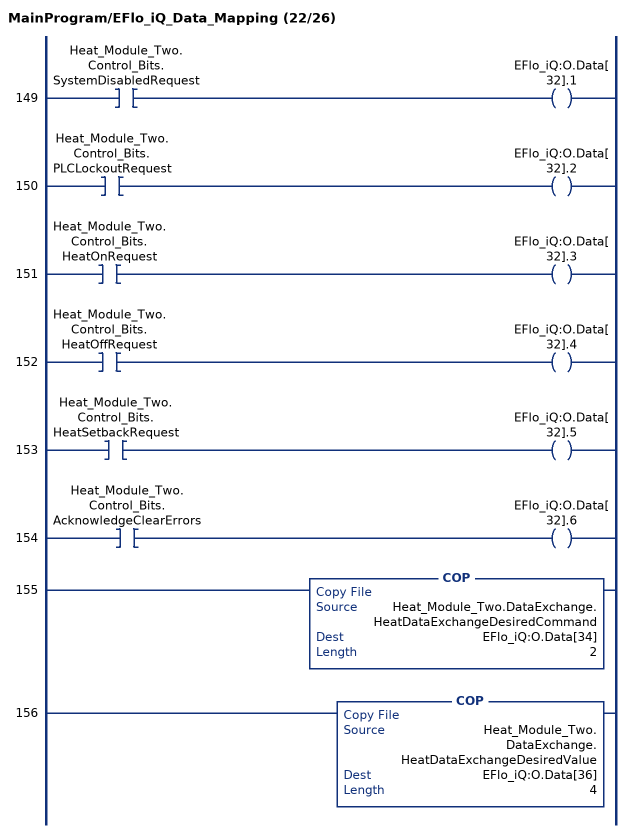
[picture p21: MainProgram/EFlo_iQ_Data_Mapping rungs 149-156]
   149: XIC(Heat_Module_Two.Control_Bits.SystemDisabledRequest)OTE(EFlo_iQ:O.Data[32].1);
   150: XIC(Heat_Module_Two.Control_Bits.PLCLockoutRequest)OTE(EFlo_iQ:O.Data[32].2);
   151: XIC(Heat_Module_Two.Control_Bits.HeatOnRequest)OTE(EFlo_iQ:O.Data[32].3);
   152: XIC(Heat_Module_Two.Control_Bits.HeatOffRequest)OTE(EFlo_iQ:O.Data[32].4);
   153: XIC(Heat_Module_Two.Control_Bits.HeatSetbackRequest)OTE(EFlo_iQ:O.Data[32].5);
   154: XIC(Heat_Module_Two.Control_Bits.AcknowledgeClearErrors)OTE(EFlo_iQ:O.Data[32].6);
   155: COP(Heat_Module_Two.DataExchange.HeatDataExchangeDesiredCommand,EFlo_iQ:O.Data[34],2);
   156: COP(Heat_Module_Two.DataExchange.HeatDataExchangeDesiredValue,EFlo_iQ:O.Data[36],4);
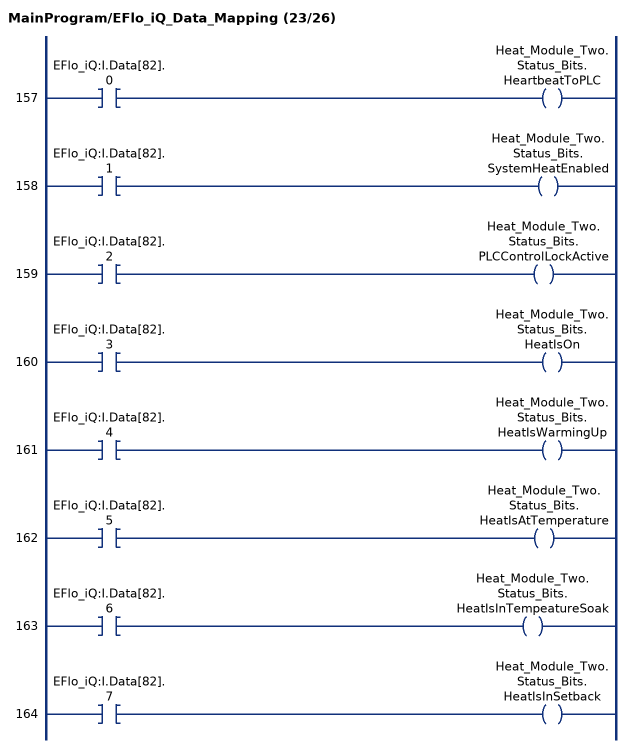
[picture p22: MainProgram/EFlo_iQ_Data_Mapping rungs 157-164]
   157: XIC(EFlo_iQ:I.Data[82].0)OTE(Heat_Module_Two.Status_Bits.HeartbeatToPLC);
   158: XIC(EFlo_iQ:I.Data[82].1)OTE(Heat_Module_Two.Status_Bits.SystemHeatEnabled);
   159: XIC(EFlo_iQ:I.Data[82].2)OTE(Heat_Module_Two.Status_Bits.PLCControlLockActive);
   160: XIC(EFlo_iQ:I.Data[82].3)OTE(Heat_Module_Two.Status_Bits.HeatIsOn);
   161: XIC(EFlo_iQ:I.Data[82].4)OTE(Heat_Module_Two.Status_Bits.HeatIsWarmingUp);
   162: XIC(EFlo_iQ:I.Data[82].5)OTE(Heat_Module_Two.Status_Bits.HeatIsAtTemperature);
   163: XIC(EFlo_iQ:I.Data[82].6)OTE(Heat_Module_Two.Status_Bits.HeatIsInTempeatureSoak);
   164: XIC(EFlo_iQ:I.Data[82].7)OTE(Heat_Module_Two.Status_Bits.HeatIsInSetback);
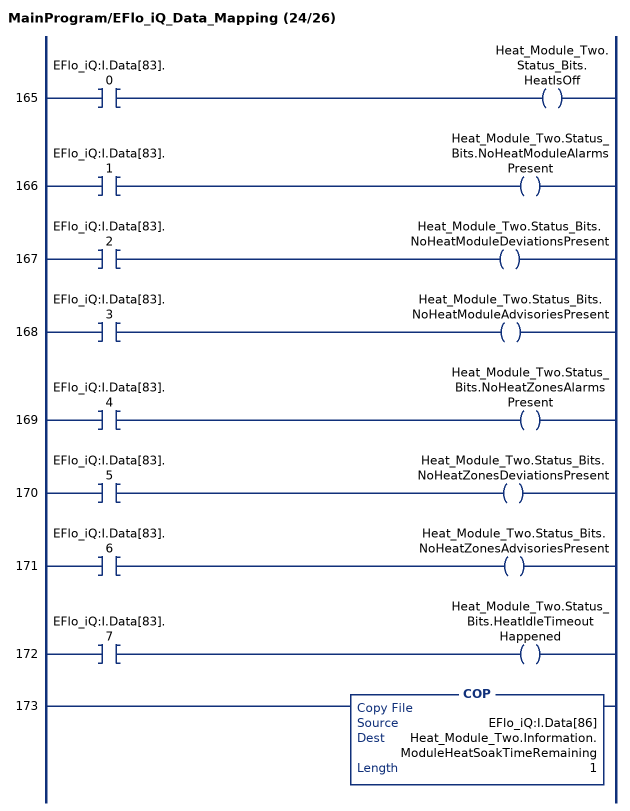
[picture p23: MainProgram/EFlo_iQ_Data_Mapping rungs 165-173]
   165: XIC(EFlo_iQ:I.Data[83].0)OTE(Heat_Module_Two.Status_Bits.HeatIsOff);
   166: XIC(EFlo_iQ:I.Data[83].1)OTE(Heat_Module_Two.Status_Bits.NoHeatModuleAlarmsPresent);
   167: XIC(EFlo_iQ:I.Data[83].2)OTE(Heat_Module_Two.Status_Bits.NoHeatModuleDeviationsPresent);
   168: XIC(EFlo_iQ:I.Data[83].3)OTE(Heat_Module_Two.Status_Bits.NoHeatModuleAdvisoriesPresent);
   169: XIC(EFlo_iQ:I.Data[83].4)OTE(Heat_Module_Two.Status_Bits.NoHeatZonesAlarmsPresent);
   170: XIC(EFlo_iQ:I.Data[83].5)OTE(Heat_Module_Two.Status_Bits.NoHeatZonesDeviationsPresent);
   171: XIC(EFlo_iQ:I.Data[83].6)OTE(Heat_Module_Two.Status_Bits.NoHeatZonesAdvisoriesPresent);
   172: XIC(EFlo_iQ:I.Data[83].7)OTE(Heat_Module_Two.Status_Bits.HeatIdleTimeoutHappened);
   173: COP(EFlo_iQ:I.Data[86],Heat_Module_Two.Information.ModuleHeatSoakTimeRemaining,1);
